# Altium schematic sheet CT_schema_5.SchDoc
size 322 x 302 mm
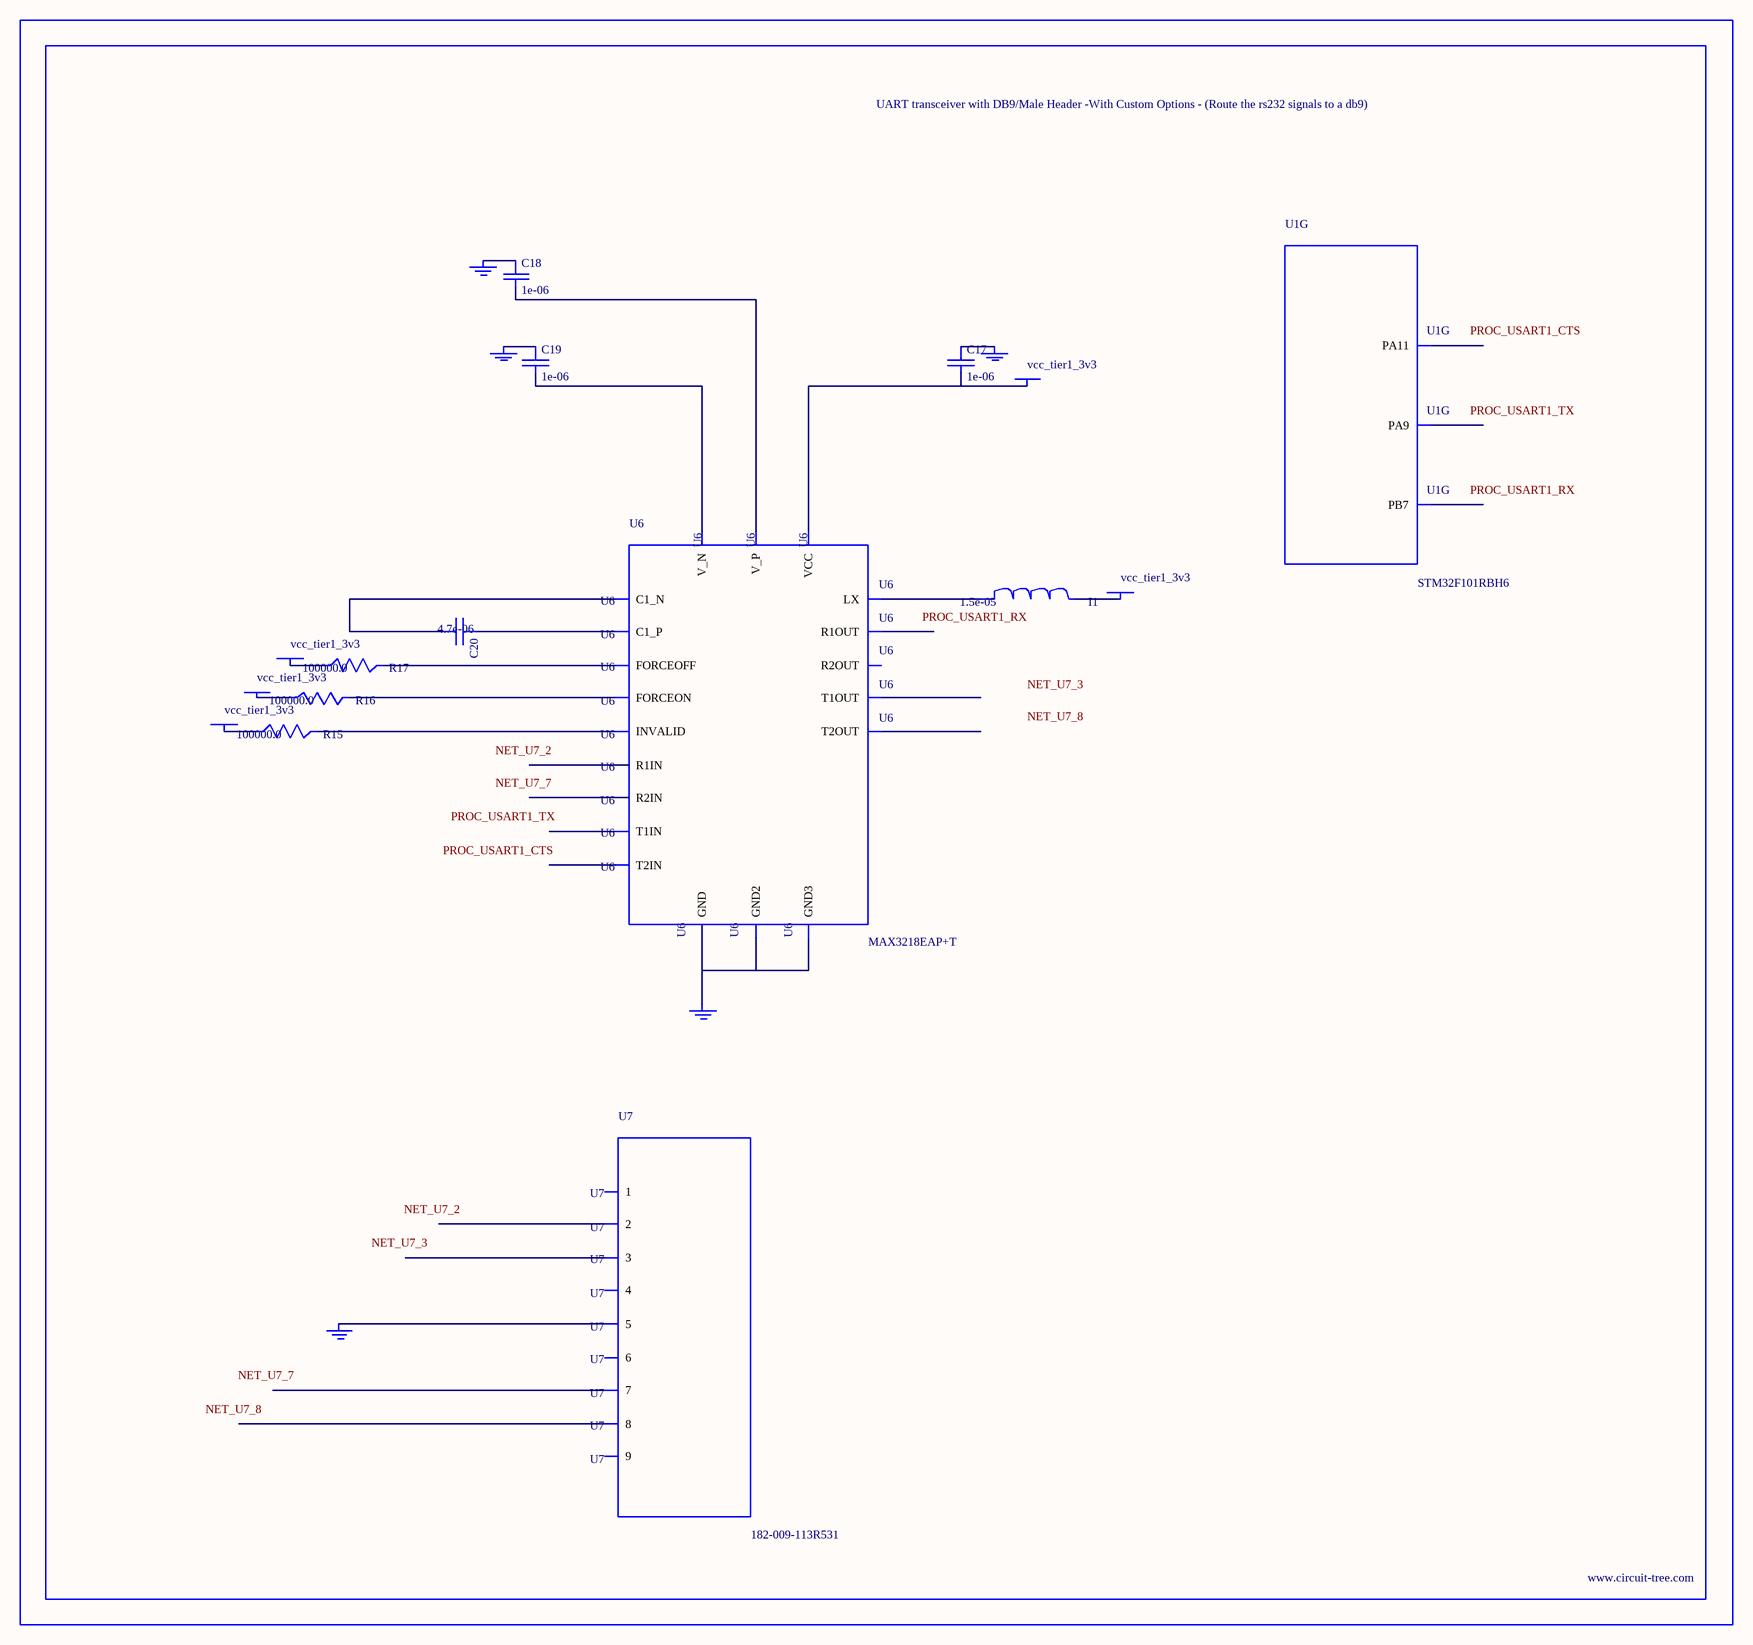
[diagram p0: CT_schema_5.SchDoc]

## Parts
BORDER4  (no value)
C17  1e-06  [C0603]
C18  1e-06  [C0603]
C19  1e-06  [C0603]
C20  4.7e-06  [C0805]
GND_INSTANCE_4_0  (no value)
GND_INSTANCE_4_1  (no value)
GND_INSTANCE_4_2  (no value)
GND_INSTANCE_4_3  (no value)
GND_INSTANCE_4_4  (no value)
I1  1.5e-05  [L1210]
POWER_INSTANCE_4_0  vcc_tier1_3v3
POWER_INSTANCE_4_1  vcc_tier1_3v3
POWER_INSTANCE_4_2  vcc_tier1_3v3
POWER_INSTANCE_4_3  vcc_tier1_3v3
POWER_INSTANCE_4_4  vcc_tier1_3v3
R15  100000.0  [R0603]
R16  100000.0  [R0603]
R17  100000.0  [R0603]
U1  STM32F101RBH6  [TFBGA64]  (part G of 7)
U6  MAX3218EAP+T  [SSOP-20]
U7  182-009-113R531  [182-009-MALE]

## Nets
NetC17_1: C17.1 GND_INSTANCE_4_0.0(GND)
NetC17_2: C17.2 POWER_INSTANCE_4_4.0(PWR) U6.6(VCC)
NetC18_1: C18.1 GND_INSTANCE_4_2.0(GND)
NetC18_2: C18.2 U6.19(V_P)
NetC19_1: C19.1 GND_INSTANCE_4_1.0(GND)
NetC19_2: C19.2 U6.15(V_N)
NetC20_1: C20.1 U6.18(C1_P)
NetC20_2: C20.2 U6.16(C1_N)
NetGND_INSTANCE_4_3_0: GND_INSTANCE_4_3.0(GND) U6.5(GND) U6.17(GND2) U6.20(GND3)
NetGND_INSTANCE_4_4_0: GND_INSTANCE_4_4.0(GND) U7.5
NetI1_1: I1.1 U6.1(LX)
NetI1_2: I1.2 POWER_INSTANCE_4_0.0(PWR)
NetPOWER_INSTANCE_4_1_0: POWER_INSTANCE_4_1.0(PWR) R15.1
NetPOWER_INSTANCE_4_2_0: POWER_INSTANCE_4_2.0(PWR) R16.1
NetPOWER_INSTANCE_4_3_0: POWER_INSTANCE_4_3.0(PWR) R17.1
NetR15_2: R15.2 U6.2(INVALID)
NetR16_2: R16.2 U6.3(FORCEON)
NetR17_2: R17.2 U6.4(FORCEOFF)

Not connected (* = marked no-connect by the designer): U1 C3(PB7) C7(PA9) C8(PA11); U6 7(T1IN) 8(T2IN) 9(R1OUT) 10(R2OUT) 11(R2IN) 12(R1IN) 13(T2OUT) 14(T1OUT); U7 1 2 3 4 6 7 8 9

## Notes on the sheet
- Labels drawn without touching a wire or pin: NET_U7_2, NET_U7_3, NET_U7_7, NET_U7_8, PROC_USART1_CTS, PROC_USART1_RX, PROC_USART1_TX

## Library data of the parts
BORDER4 = BORDER_PAGE4
C17-C19 = C0603C105K3RACTU
C20 = C0805C475K4RACTU
GND_INSTANCE_4_0-GND_INSTANCE_4_4 = GND
I1 = L1210R150MDWIT
POWER_INSTANCE_4_0-POWER_INSTANCE_4_4 = PWR
R15-R17 = RC0603JR-07100KL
